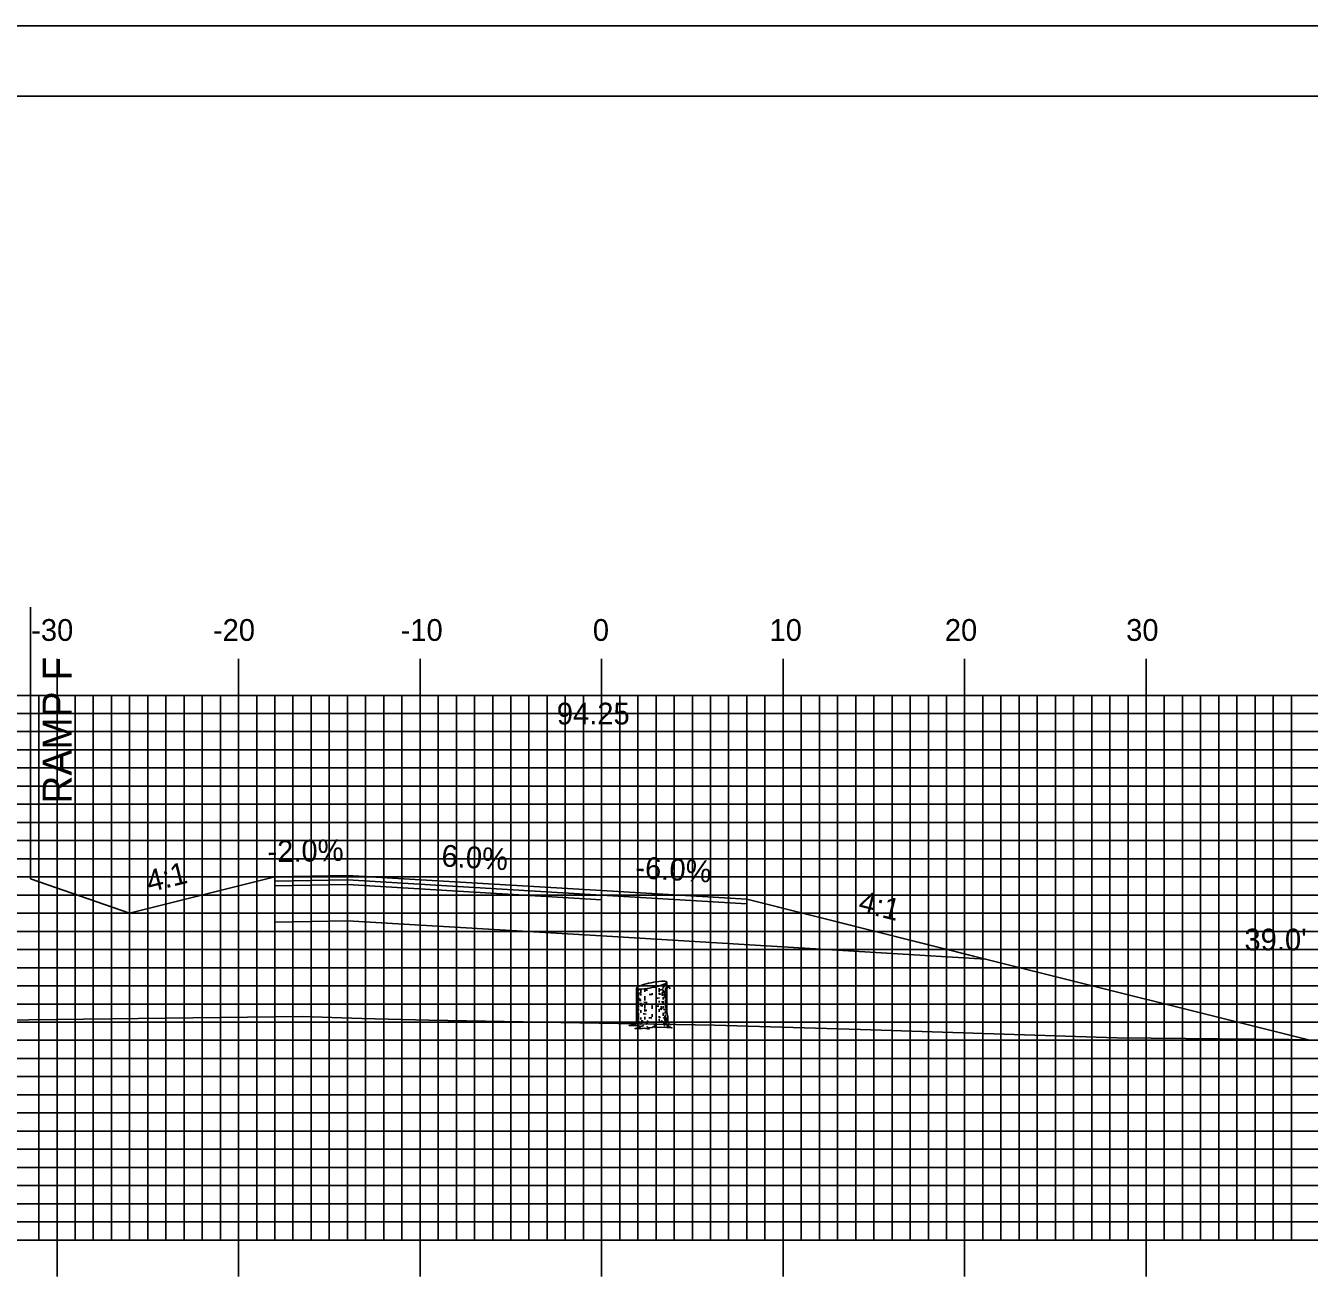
# Model space of a CAD drawing. Extents: x 854116 to 854460, y 364366 to 364586.
# Drawn here: x 854250.5 to 854321.2, y 364516.3 to 364585.7 of the extents above; entities that cross this region are included whole.
import ezdxf

# ---------------------------------------------------------------- set-up
doc = ezdxf.new("R2010")
doc.units = 0
for name, color, linetype in [('ANNOTATION', 7, 'Continuous'), ('BORDER', 7, 'Continuous'), ('D_Roadway_Centerline', 7, 'Continuous'), ('D_Roadway_Centerline_Text', 7, 'Continuous'), ('D_Roadway_Edge_Shoulder', 7, 'Continuous'), ('D_Roadway_Edge_TW', 7, 'Continuous'), ('D_Roadway_Pavement', 7, 'Continuous'), ('D_Roadway_SlopeLines', 7, 'Continuous'), ('D_Roadway_SubGrade', 7, 'Continuous'), ('D_Text_Standard', 7, 'Continuous'), ('H_V ANNOTATION', 7, 'Continuous'), ('M_Trees_Conifer_Pay', 7, 'Continuous'), ('MAJOR', 7, 'Continuous'), ('MINOR', 7, 'Continuous'), ('PLOT BOUNDARY', 7, 'Continuous'), ('S_Roadway_Centerline', 7, 'Continuous')]:
    doc.layers.add(name, color=color, linetype=linetype)

msp = doc.modelspace()

# ---------------------------------------------------------------- linework, layer by layer
at = {"layer": 'BORDER'}
msp.add_lwpolyline([(854132.631, 364371.787), (854452.631, 364371.787), (854452.631, 364581.787), (854132.631, 364581.787)], close=True, dxfattribs=at)
at = {"layer": 'D_Roadway_Centerline'}
msp.add_lwpolyline([(854250.778, 364538.684), (854256.231, 364536.794), (854264.231, 364538.794), (854268.231, 364538.874), (854282.231, 364538.034), (854290.231, 364537.554), (854302.231, 364534.554), (854303.389, 364534.265), (854321.182, 364529.816)], dxfattribs=at)
at = {"layer": 'D_Roadway_Edge_Shoulder'}
for points in [[(854268.231, 364538.874), (854264.231, 364538.794), (854264.231, 364538.544), (854268.231, 364538.624)], [(854282.231, 364538.034), (854290.231, 364537.554), (854290.231, 364537.304), (854282.231, 364537.784)]]:
    msp.add_lwpolyline(points, close=True, dxfattribs=at)
at = {"layer": 'D_Roadway_Edge_TW'}
msp.add_lwpolyline([(854268.231, 364538.874), (854282.231, 364538.034), (854282.231, 364537.784), (854268.231, 364538.624)], close=True, dxfattribs=at)
at = {"layer": 'D_Roadway_Pavement'}
for points in [[(854268.231, 364538.624), (854264.231, 364538.544), (854264.231, 364538.294), (854268.231, 364538.374)], [(854268.231, 364538.624), (854282.231, 364537.784), (854282.231, 364537.534), (854268.231, 364538.374)]]:
    msp.add_lwpolyline(points, close=True, dxfattribs=at)
msp.add_lwpolyline([(854282.231, 364537.784), (854282.231, 364537.534)], dxfattribs=at)
msp.add_lwpolyline([(854282.231, 364537.784), (854282.231, 364537.534)], dxfattribs=at)
at = {"layer": 'D_Roadway_SlopeLines'}
msp.add_lwpolyline([(854290.231, 364537.554), (854303.389, 364534.265), (854321.182, 364529.816)], dxfattribs=at)
at = {"layer": 'D_Roadway_SubGrade'}
msp.add_line((854250.778, 364553.641), (854250.778, 364538.684), dxfattribs=at)
for points in [[(854268.231, 364538.374), (854264.231, 364538.294), (854264.231, 364538.544), (854264.231, 364538.794), (854264.231, 364536.294), (854268.231, 364536.374)], [(854268.231, 364538.374), (854282.231, 364537.534), (854282.231, 364535.534), (854268.231, 364536.374)], [(854282.231, 364537.534), (854282.231, 364537.784), (854290.231, 364537.304), (854290.231, 364537.554), (854303.389, 364534.265), (854282.231, 364535.534)]]:
    msp.add_lwpolyline(points, close=True, dxfattribs=at)
at = {"layer": 'M_Trees_Conifer_Pay'}
for p, q in [((854285.82, 364531.345), (854285.82, 364532.992)), ((854284.156, 364530.935), (854284.156, 364532.657)), ((854284.204, 364532.62), (854284.204, 364532.148)), ((854284.262, 364532.608), (854284.262, 364532.511)), ((854284.262, 364532.436), (854284.262, 364532.232)), ((854284.387, 364532.6), (854284.387, 364532.368)), ((854284.387, 364532.328), (854284.387, 364532.253)), ((854284.607, 364532.621), (854284.607, 364532.453)), ((854285.013, 364532.389), (854285.013, 364532.294)), ((854285.403, 364532.663), (854285.403, 364532.463)), ((854285.403, 364532.406), (854285.403, 364532.317)), ((854285.631, 364532.859), (854285.631, 364532.636)), ((854285.631, 364532.547), (854285.631, 364532.5)), ((854285.688, 364532.364), (854285.637, 364532.305)), ((854285.749, 364532.92), (854285.749, 364532.757)), ((854285.749, 364532.69), (854285.749, 364532.562)), ((854285.749, 364532.375), (854285.749, 364532.039)), ((854284.204, 364532.084), (854284.204, 364531.776)), ((854284.204, 364531.728), (854284.204, 364531.236)), ((854284.262, 364532.175), (854284.262, 364531.975)), ((854284.262, 364531.928), (854284.262, 364531.592)), ((854284.262, 364531.539), (854284.262, 364531.403)), ((854284.387, 364531.85), (854284.387, 364531.711)), ((854284.607, 364532.216), (854284.607, 364531.979)), ((854284.607, 364531.734), (854284.607, 364531.582)), ((854284.607, 364531.539), (854284.607, 364531.366)), ((854285.013, 364531.776), (854285.013, 364531.702)), ((854285.013, 364531.677), (854285.013, 364531.528)), ((854285.403, 364531.969), (854285.403, 364531.864)), ((854285.631, 364532.165), (854285.631, 364532.033)), ((854285.631, 364531.922), (854285.631, 364531.812)), ((854285.631, 364531.677), (854285.631, 364531.535)), ((854285.749, 364532.002), (854285.749, 364531.839)), ((854285.749, 364531.792), (854285.749, 364531.576)), ((854285.749, 364531.545), (854285.749, 364531.471)), ((854284.204, 364531.183), (854284.204, 364530.935)), ((854284.262, 364531.304), (854284.262, 364530.925)), ((854284.387, 364531.44), (854284.387, 364531.298)), ((854284.387, 364531.036), (854284.387, 364530.942)), ((854284.607, 364531.088), (854284.607, 364530.935)), ((854285.013, 364531.236), (854285.013, 364531.083)), ((854285.403, 364531.497), (854285.403, 364531.351)), ((854285.403, 364531.119), (854285.403, 364531.03)), ((854285.631, 364531.308), (854285.631, 364531.135)), ((854285.749, 364531.43), (854285.749, 364531.257)), ((854284.387, 364530.542), (854284.55, 364530.606)), ((854284.824, 364530.478), (854284.698, 364530.542))]:
    msp.add_line(p, q, dxfattribs=at)
for points in [[(854285.604, 364532.453), (854285.573, 364532.368), (854285.569, 364532.301), (854285.6, 364532.237)], [(854285.637, 364532.49), (854285.674, 364532.416), (854285.721, 364532.473), (854285.779, 364532.541), (854285.871, 364532.735), (854285.936, 364532.782), (854285.967, 364532.789)], [(854285.652, 364532.237), (854285.688, 364532.364), (854285.752, 364532.48), (854285.783, 364532.547), (854285.852, 364532.694)], [(854285.866, 364532.723), (854285.942, 364532.731), (854286.014, 364532.632)], [(854284.335, 364531.963), (854284.329, 364532.058), (854284.373, 364532.035), (854284.373, 364531.94)], [(854285.474, 364531.564), (854285.487, 364531.487), (854285.534, 364531.497), (854285.522, 364531.664)], [(854285.82, 364531.345), (854285.871, 364531.083), (854285.888, 364530.81), (854285.946, 364530.684), (854286.081, 364530.654), (854285.851, 364530.616), (854285.851, 364530.616), (854285.857, 364530.569), (854286.104, 364530.475), (854285.83, 364530.491), (854285.474, 364530.511), (854285.153, 364530.501), (854285.16, 364530.583), (854285.011, 364530.501), (854284.824, 364530.478), (854284.849, 364530.41), (854284.581, 364530.454), (854284.36, 364530.427), (854284.068, 364530.444), (854284.356, 364530.501), (854284.387, 364530.542), (854284.224, 364530.6), (854283.988, 364530.61), (854283.747, 364530.61), (854284.089, 364530.668), (854284.13, 364530.748), (854284.156, 364530.935)], [(854284.204, 364530.888), (854284.183, 364530.81), (854284.163, 364530.715)], [(854284.282, 364530.868), (854284.288, 364530.752), (854284.235, 364530.663), (854284.224, 364530.6)], [(854284.445, 364530.894), (854284.445, 364530.763), (854284.356, 364530.663)], [(854284.671, 364530.654), (854284.739, 364530.748), (854284.766, 364530.888)], [(854285.16, 364530.583), (854285.234, 364530.725), (854285.244, 364530.826)], [(854285.41, 364530.952), (854285.421, 364530.826), (854285.495, 364530.783)], [(854285.688, 364530.563), (854285.674, 364530.701), (854285.6, 364530.83)], [(854285.647, 364531.057), (854285.721, 364530.952), (854285.726, 364530.779), (854285.851, 364530.616)], [(854285.746, 364531.203), (854285.752, 364531.057), (854285.799, 364530.989), (854285.81, 364530.789)]]:
    msp.add_lwpolyline(points, dxfattribs=at)
for centre, radius, start, end in [((854286.012, 364527.889), 5.179, 101.7194, 108.05939), ((854286.012, 364527.889), 5.179, 95.37941, 101.7194), ((854285.602, 364532.247), 0.802, 79.2194, 95.37941), ((854285.705, 364532.789), 0.251, 71.05013, 79.2194), ((854285.631, 364533.142), 0.251, 304.2194, 312.38868), ((854285.76, 364532.948), 0.0817, 56.7194, 71.05013), ((854285.745, 364533.018), 0.0817, 312.38868, 326.7194), ((854285.776, 364532.973), 0.0527, 46.92298, 56.7194), ((854285.79, 364532.988), 0.0314, 34.2194, 46.92298), ((854285.769, 364533.002), 0.0527, 326.7194, 336.51582), ((854285.794, 364532.991), 0.0264, 23.40735, 34.2194), ((854285.789, 364532.993), 0.0314, 336.51582, 349.2194), ((854285.798, 364532.992), 0.0226, 11.7194, 23.40735), ((854285.798, 364532.992), 0.0226, 0.03145, 11.7194), ((854285.794, 364532.992), 0.0264, 349.2194, 0.03145), ((854284.188, 364532.479), 0.0334, 163.94846, 180), ((854284.188, 364532.479), 0.0334, 180, 196.05154), ((854284.183, 364532.657), 0.0264, 169.2194, 180.03145), ((854284.179, 364532.657), 0.0226, 180.03145, 191.7194), ((854284.199, 364532.482), 0.0441, 196.05154, 210), ((854284.188, 364532.656), 0.0314, 156.51582, 169.2194), ((854284.179, 364532.657), 0.0226, 191.7194, 203.40735), ((854284.182, 364532.658), 0.0264, 203.40735, 214.2194), ((854284.207, 364532.647), 0.0527, 146.7194, 156.51582), ((854284.187, 364532.661), 0.0314, 214.2194, 226.92298), ((854284.215, 364532.491), 0.0624, 210, 228.74941), ((854284.231, 364532.631), 0.0817, 132.38868, 146.7194), ((854284.201, 364532.677), 0.0527, 226.92298, 236.7194), ((854284.217, 364532.701), 0.0817, 236.7194, 251.05013), ((854284.287, 364532.573), 0.172, 228.74941, 240), ((854284.345, 364532.507), 0.251, 124.2194, 132.38868), ((854284.272, 364532.86), 0.251, 251.05013, 259.2194), ((854284.486, 364532.918), 0.571, 240, 240.33672), ((854284.655, 364532.051), 0.802, 108.05939, 124.2194), ((854284.375, 364533.402), 0.802, 259.2194, 275.37941), ((854284.486, 364532.918), 0.571, 246.85973, 257.98457), ((854283.965, 364537.76), 5.179, 275.37941, 281.7194), ((854284.989, 364536.669), 4.124, 264.6955, 266.73309), ((854284.987, 364536.436), 4.124, 268.07512, 270), ((854284.987, 364536.436), 4.124, 270, 270.35814), ((854283.965, 364537.76), 5.179, 281.7194, 288.05939), ((854284.987, 364536.436), 4.124, 275.78493, 277.05584), ((854284.989, 364536.669), 4.124, 276.23804, 278.1032), ((854285.322, 364533.598), 0.802, 288.05939, 304.2194), ((854285.489, 364533.151), 0.571, 278.1032, 284.36665), ((854285.489, 364533.306), 0.571, 284.43166, 292.41325), ((854285.489, 364533.151), 0.571, 297.0237, 300), ((854285.689, 364532.961), 0.172, 300, 311.25059), ((854285.689, 364532.806), 0.172, 300, 311.25059), ((854285.761, 364532.878), 0.0624, 311.25059, 330), ((854285.761, 364532.724), 0.0624, 311.25059, 330), ((854285.777, 364532.869), 0.0441, 330, 343.94846), ((854285.777, 364532.715), 0.0441, 330, 343.94846), ((854285.787, 364532.866), 0.0334, 343.94846, 354.21506), ((854285.787, 364532.712), 0.0334, 343.94846, 354.21506), ((854285.787, 364532.268), 0.0334, 343.94846, 354.21506), ((854284.188, 364532.032), 0.0334, 163.94846, 180), ((854284.188, 364532.032), 0.0334, 180, 196.05154), ((854284.188, 364531.822), 0.0334, 163.94846, 180), ((854284.188, 364531.822), 0.0334, 180, 196.05154), ((854284.188, 364531.585), 0.0334, 163.94846, 180), ((854284.188, 364531.585), 0.0334, 180, 196.05154), ((854284.199, 364532.035), 0.0441, 196.05154, 210), ((854284.199, 364531.825), 0.0441, 196.05154, 210), ((854284.199, 364531.588), 0.0441, 196.05154, 210), ((854284.215, 364532.044), 0.0624, 210, 228.74941), ((854284.215, 364531.834), 0.0624, 210, 228.74941), ((854284.215, 364531.597), 0.0624, 210, 228.74941), ((854284.287, 364532.127), 0.172, 228.74941, 240), ((854284.287, 364531.917), 0.172, 228.74941, 240), ((854284.287, 364531.68), 0.172, 228.74941, 240), ((854284.486, 364532.472), 0.571, 240, 240.33672), ((854284.486, 364532.262), 0.571, 240, 246.85973), ((854284.486, 364532.025), 0.571, 240, 246.85973), ((854284.488, 364532.707), 0.571, 240, 247.05866), ((854284.486, 364532.262), 0.571, 259.27072, 261.8968), ((854284.987, 364535.779), 4.124, 261.8968, 263.14738), ((854284.987, 364535.989), 4.124, 264.08098, 266.66759), ((854284.987, 364535.779), 4.124, 270, 270.35814), ((854284.987, 364535.779), 4.124, 273.14934, 275.45691), ((854284.988, 364536.225), 4.124, 273.70524, 275.95043), ((854284.987, 364535.989), 4.124, 277.61247, 278.1032), ((854285.488, 364532.472), 0.571, 278.1032, 286.92962), ((854285.489, 364532.707), 0.571, 284.44928, 297.04285), ((854285.488, 364532.472), 0.571, 297.18959, 300), ((854285.488, 364532.262), 0.571, 297.18959, 300), ((854285.687, 364532.127), 0.172, 300, 311.25059), ((854285.687, 364531.917), 0.172, 300, 311.25059), ((854285.76, 364532.044), 0.0624, 311.25059, 330), ((854285.76, 364531.834), 0.0624, 311.25059, 330), ((854285.775, 364532.035), 0.0441, 330, 343.94846), ((854285.775, 364531.825), 0.0441, 330, 343.94846), ((854285.786, 364532.032), 0.0334, 343.94846, 354.21506), ((854285.786, 364531.822), 0.0334, 343.94846, 354.21506), ((854284.188, 364531.387), 0.0334, 163.94846, 180), ((854284.188, 364531.192), 0.0334, 163.94846, 180), ((854284.188, 364531.192), 0.0334, 180, 196.05154), ((854284.188, 364530.971), 0.0334, 163.94846, 180), ((854284.188, 364530.971), 0.0334, 180, 196.05154), ((854284.199, 364531.195), 0.0441, 196.05154, 210), ((854284.199, 364530.974), 0.0441, 196.05154, 210), ((854284.215, 364531.204), 0.0624, 210, 228.74941), ((854284.215, 364530.984), 0.0624, 210, 228.74941), ((854284.287, 364531.287), 0.172, 228.74941, 240), ((854284.287, 364531.066), 0.172, 228.74941, 240), ((854284.476, 364531.833), 0.571, 241.23686, 248.02677), ((854284.486, 364531.632), 0.571, 240, 246.85973), ((854284.486, 364531.411), 0.571, 240, 244.53138), ((854284.987, 364534.929), 4.124, 262.44379, 263.51202), ((854284.987, 364535.345), 4.124, 263.49906, 265.83975), ((854284.987, 364535.542), 4.124, 264.71603, 266.31934), ((854284.987, 364535.149), 4.124, 267.81166, 270), ((854284.987, 364535.149), 4.124, 270, 270.13279), ((854284.987, 364535.149), 4.124, 275.78493, 276.78961), ((854284.987, 364534.929), 4.124, 277.36842, 278.1032), ((854285.488, 364531.411), 0.571, 278.1032, 281.63703), ((854285.488, 364532.025), 0.571, 285.39827, 297.18959), ((854285.488, 364531.632), 0.571, 288.50673, 297.27208), ((854285.488, 364531.827), 0.571, 289.29072, 300), ((854285.687, 364531.482), 0.172, 300, 311.25059), ((854285.687, 364531.066), 0.172, 300, 311.25059), ((854285.76, 364531.4), 0.0624, 311.25059, 330), ((854285.76, 364530.984), 0.0624, 311.25059, 330), ((854285.775, 364531.39), 0.0441, 330, 343.94846), ((854285.775, 364530.974), 0.0441, 330, 343.94846), ((854285.786, 364531.387), 0.0334, 343.94846, 354.21506), ((854285.786, 364530.971), 0.0334, 343.94846, 354.21506)]:
    msp.add_arc(centre, radius, start, end, dxfattribs=at)
at = {"layer": 'MAJOR'}
for p, q in [((854252.231, 364550.791), (854252.231, 364548.787)), ((854262.231, 364550.791), (854262.231, 364548.787)), ((854272.231, 364550.791), (854272.231, 364548.787)), ((854282.231, 364550.791), (854282.231, 364548.787)), ((854292.231, 364550.791), (854292.231, 364548.787)), ((854302.231, 364550.791), (854302.231, 364548.787)), ((854312.231, 364550.791), (854312.231, 364548.787)), ((854142.231, 364548.787), (854422.231, 364548.787)), ((854142.231, 364548.787), (854422.231, 364548.787)), ((854252.231, 364518.787), (854252.231, 364548.787)), ((854262.231, 364518.787), (854262.231, 364548.787)), ((854272.231, 364518.787), (854272.231, 364548.787)), ((854282.231, 364518.787), (854282.231, 364548.787)), ((854292.231, 364518.787), (854292.231, 364548.787)), ((854302.231, 364518.787), (854302.231, 364548.787)), ((854312.231, 364518.787), (854312.231, 364548.787)), ((854142.231, 364543.787), (854422.231, 364543.787)), ((854142.231, 364538.787), (854422.231, 364538.787)), ((854142.231, 364533.787), (854422.231, 364533.787)), ((854142.231, 364528.787), (854422.231, 364528.787)), ((854142.231, 364523.787), (854422.231, 364523.787)), ((854142.231, 364518.787), (854422.231, 364518.787)), ((854142.231, 364518.787), (854422.231, 364518.787)), ((854252.231, 364516.783), (854252.231, 364518.787)), ((854262.231, 364516.783), (854262.231, 364518.787)), ((854272.231, 364516.783), (854272.231, 364518.787)), ((854282.231, 364516.783), (854282.231, 364518.787)), ((854292.231, 364516.783), (854292.231, 364518.787)), ((854302.231, 364516.783), (854302.231, 364518.787)), ((854312.231, 364516.783), (854312.231, 364518.787))]:
    msp.add_line(p, q, dxfattribs=at)
at = {"layer": 'MINOR'}
for p, q in [((854251.231, 364518.787), (854251.231, 364548.787)), ((854253.231, 364518.787), (854253.231, 364548.787)), ((854254.231, 364518.787), (854254.231, 364548.787)), ((854255.231, 364518.787), (854255.231, 364548.787)), ((854256.231, 364518.787), (854256.231, 364548.787)), ((854257.231, 364518.787), (854257.231, 364548.787)), ((854258.231, 364518.787), (854258.231, 364548.787)), ((854259.231, 364518.787), (854259.231, 364548.787)), ((854260.231, 364518.787), (854260.231, 364548.787)), ((854261.231, 364518.787), (854261.231, 364548.787)), ((854263.231, 364518.787), (854263.231, 364548.787)), ((854264.231, 364518.787), (854264.231, 364548.787)), ((854265.231, 364518.787), (854265.231, 364548.787)), ((854266.231, 364518.787), (854266.231, 364548.787)), ((854267.231, 364518.787), (854267.231, 364548.787)), ((854268.231, 364518.787), (854268.231, 364548.787)), ((854269.231, 364518.787), (854269.231, 364548.787)), ((854270.231, 364518.787), (854270.231, 364548.787)), ((854271.231, 364518.787), (854271.231, 364548.787)), ((854273.231, 364518.787), (854273.231, 364548.787)), ((854274.231, 364518.787), (854274.231, 364548.787)), ((854275.231, 364518.787), (854275.231, 364548.787)), ((854276.231, 364518.787), (854276.231, 364548.787)), ((854277.231, 364518.787), (854277.231, 364548.787)), ((854278.231, 364518.787), (854278.231, 364548.787)), ((854279.231, 364518.787), (854279.231, 364548.787)), ((854280.231, 364518.787), (854280.231, 364548.787)), ((854281.231, 364518.787), (854281.231, 364548.787)), ((854283.231, 364518.787), (854283.231, 364548.787)), ((854284.231, 364518.787), (854284.231, 364548.787)), ((854285.231, 364518.787), (854285.231, 364548.787)), ((854286.231, 364518.787), (854286.231, 364548.787)), ((854287.231, 364518.787), (854287.231, 364548.787)), ((854288.231, 364518.787), (854288.231, 364548.787)), ((854289.231, 364518.787), (854289.231, 364548.787)), ((854290.231, 364518.787), (854290.231, 364548.787)), ((854291.231, 364518.787), (854291.231, 364548.787)), ((854293.231, 364518.787), (854293.231, 364548.787)), ((854294.231, 364518.787), (854294.231, 364548.787)), ((854295.231, 364518.787), (854295.231, 364548.787)), ((854296.231, 364518.787), (854296.231, 364548.787)), ((854297.231, 364518.787), (854297.231, 364548.787)), ((854298.231, 364518.787), (854298.231, 364548.787)), ((854299.231, 364518.787), (854299.231, 364548.787)), ((854300.231, 364518.787), (854300.231, 364548.787)), ((854301.231, 364518.787), (854301.231, 364548.787)), ((854303.231, 364518.787), (854303.231, 364548.787)), ((854304.231, 364518.787), (854304.231, 364548.787)), ((854305.231, 364518.787), (854305.231, 364548.787)), ((854306.231, 364518.787), (854306.231, 364548.787)), ((854307.231, 364518.787), (854307.231, 364548.787)), ((854308.231, 364518.787), (854308.231, 364548.787)), ((854309.231, 364518.787), (854309.231, 364548.787)), ((854310.231, 364518.787), (854310.231, 364548.787)), ((854311.231, 364518.787), (854311.231, 364548.787)), ((854313.231, 364518.787), (854313.231, 364548.787)), ((854314.231, 364518.787), (854314.231, 364548.787)), ((854315.231, 364518.787), (854315.231, 364548.787)), ((854316.231, 364518.787), (854316.231, 364548.787)), ((854317.231, 364518.787), (854317.231, 364548.787)), ((854318.231, 364518.787), (854318.231, 364548.787)), ((854319.231, 364518.787), (854319.231, 364548.787)), ((854320.231, 364518.787), (854320.231, 364548.787)), ((854142.231, 364547.787), (854422.231, 364547.787)), ((854142.231, 364546.787), (854422.231, 364546.787)), ((854142.231, 364545.787), (854422.231, 364545.787)), ((854142.231, 364544.787), (854422.231, 364544.787)), ((854142.231, 364542.787), (854422.231, 364542.787)), ((854142.231, 364541.787), (854422.231, 364541.787)), ((854142.231, 364540.787), (854422.231, 364540.787)), ((854142.231, 364539.787), (854422.231, 364539.787)), ((854142.231, 364537.787), (854422.231, 364537.787)), ((854142.231, 364536.787), (854422.231, 364536.787)), ((854142.231, 364535.787), (854422.231, 364535.787)), ((854142.231, 364534.787), (854422.231, 364534.787)), ((854142.231, 364532.787), (854422.231, 364532.787)), ((854142.231, 364531.787), (854422.231, 364531.787)), ((854142.231, 364530.787), (854422.231, 364530.787)), ((854142.231, 364529.787), (854422.231, 364529.787)), ((854142.231, 364527.787), (854422.231, 364527.787)), ((854142.231, 364526.787), (854422.231, 364526.787)), ((854142.231, 364525.787), (854422.231, 364525.787)), ((854142.231, 364524.787), (854422.231, 364524.787)), ((854142.231, 364522.787), (854422.231, 364522.787)), ((854142.231, 364521.787), (854422.231, 364521.787)), ((854142.231, 364520.787), (854422.231, 364520.787)), ((854142.231, 364519.787), (854422.231, 364519.787))]:
    msp.add_line(p, q, dxfattribs=at)
at = {"layer": 'PLOT BOUNDARY'}
msp.add_lwpolyline([(854116.444, 364365.669), (854456.444, 364365.669), (854456.444, 364585.669), (854116.444, 364585.669)], close=True, dxfattribs=at)
at = {"layer": 'S_Roadway_Centerline'}
msp.add_lwpolyline([(854201.889, 364531.299), (854210.625, 364531.084), (854219.649, 364530.966), (854222.654, 364530.932), (854225.668, 364530.902), (854243.314, 364530.753), (854245.482, 364530.805), (854247.643, 364530.874), (854265.737, 364531.108), (854269.021, 364530.984), (854272.716, 364530.904), (854281.027, 364530.756), (854288.447, 364530.619), (854296.489, 364530.378), (854310.613, 364529.916), (854320.107, 364529.841), (854327.157, 364529.681)], dxfattribs=at)

# ---------------------------------------------------------------- texts
at = {"layer": 'ANNOTATION'}
for s, height, rotation, p in [('RAMP F', 1.6, 90, (854253.039, 364542.822)), ('-2.0%', 1.2, 1.14576, (854263.837, 364539.587)), ('6.0%', 1.2, 356.56637, (854273.385, 364539.369)), ('4:1', 1.2, 14.03624, (854257.332, 364537.931)), ('-6.0%', 1.2, 356.56637, (854284.065, 364538.728)), ('4:1', 1.2, 345.96376, (854296.315, 364536.895))]:
    msp.add_text(s, height=height, rotation=rotation, dxfattribs=at).set_placement(p)
at = {"layer": 'D_Roadway_Centerline_Text'}
msp.add_text('94.25', height=1.2, dxfattribs=at).set_placement((854279.764, 364547.182))
at = {"layer": 'D_Text_Standard'}
msp.add_text("39.0'", height=1.2, dxfattribs=at).set_placement((854317.645, 364534.737))
at = {"layer": 'H_V ANNOTATION'}
for s, p in [('-30', (854250.807, 364551.787)), ('-20', (854260.818, 364551.787)), ('-10', (854271.16, 364551.787)), ('0', (854281.749, 364551.787)), ('10', (854291.481, 364551.787)), ('20', (854301.139, 364551.787)), ('30', (854311.128, 364551.787))]:
    msp.add_text(s, height=1.2, dxfattribs=at).set_placement(p)

doc.saveas('drawing.dxf')
